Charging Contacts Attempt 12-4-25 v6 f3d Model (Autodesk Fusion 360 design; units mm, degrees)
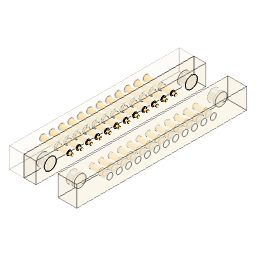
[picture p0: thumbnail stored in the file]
derived_base_feature "Derived Base Feature1" bodies "Male Pin 1"
copy_paste_bodies "CopyPasteBodies2"
move "Move2"
copy_paste_bodies "CopyPasteBodies4"
move "Move3"
copy_paste_bodies "CopyPasteBodies5"
move "Move4"
copy_paste_bodies "CopyPasteBodies6"
move "Move5"
derived_base_feature "Derived Base Feature2" bodies "Magnet (1)", "Magnet 1"
move "Move6"
move "Move7"
move "Move8"
move "Move9"
move "Move10"
move "Move11"
move "Move12"
copy_paste_bodies "CopyPasteBodies7"
move "Move13"
move "Move14"
move "Move15"
move "Move16"
align "Align1"
move "Move17"
align "Align2"
move "Move18"
remove_body "RemoveBody1"
copy_paste_bodies "CopyPasteBodies8"
move "Move19"
move "Move20"
sketch "Sketch4" plane through (0, 0, 0) normal (1, 0, 0) x axis (0, 1, 0)
  line L1 (45.2245, 5) -> (-45.0911, 5)
  line L2 (45.2245, -6) -> (45.2245, 5)
  line L3 (-45.0911, -6) -> (45.2245, -6)
  line L4 (-45.0911, 5) -> (-45.0911, -6)
  horizontal L1
  vertical L2
  horizontal L3
  vertical L4
extrude "Extrude1" new body sketch "Sketch4" along normal blind 7.849 bodies "Charger with Extrusion Female Facing"
extrude "Extrude2" cut of existing geometry blind -1.524
copy_paste_bodies "CopyPasteBodies9"
move "Move21"
copy_paste_bodies "CopyPasteBodies10"
move "Move22"
combine "Combine1"
derived_base_feature "Derived Base Feature3" bodies "0436-0-15-15-03-27-10-0", "Female Pin 1"
move "Move23"
component_from_bodies "Body->Comp"
move "Move1"
extrude "Extrude3" new body of existing geometry blind 7.874 bodies "Charger with Extrusion Wire Side"
combine "Combine2"
align "Align1"
move "Move2"
copy_paste_bodies "CopyPasteBodies1"
move "Move3"
copy_paste_bodies "CopyPasteBodies2"
move "Move4"
copy_paste_bodies "CopyPasteBodies3"
move "Move5"
copy_paste_bodies "CopyPasteBodies4"
copy_paste_bodies "CopyPasteBodies5"
move "Move6"
copy_paste_bodies "CopyPasteBodies6"
move "Move7"
sketch "Sketch1" plane through (0, 0, 0) normal (1, 0, 0) x axis (0, 1, 0)
  line L1 (45, 5) -> (-45, 5)
  line L2 (45, -6) -> (45, 5)
  line L3 (-45, -6) -> (45, -6)
  line L4 (-45, 5) -> (-45, -6)
  horizontal L1
  vertical L2
  horizontal L3
  vertical L4
sketch "Sketch2" plane through (0, 0, 0) normal (1, 0, 0) x axis (0, 1, 0)
extrude "Extrude1" new body sketch "Sketch4" along normal blind 10 bodies "Female Charger"
move "Move8"
copy_paste_bodies "CopyPasteBodies7"
move "Move9"
copy_paste_bodies "CopyPasteBodies8"
move "Move10"
move "Move11"
copy_paste_bodies "CopyPasteBodies9"
extrude "Extrude2" new body of existing geometry blind 8
copy_paste_bodies "CopyPasteBodies10"
move "Move12"
copy_paste_bodies "CopyPasteBodies11"
move "Move13"
copy_paste_bodies "CopyPasteBodies12"
move "Move14"
copy_paste_bodies "CopyPasteBodies13"
copy_paste_bodies "CopyPasteBodies14"
move "Move15"
combine "Combine1" bodies "Female Charger (1)", "Female Charger (2)", "Female Charger", "Female Charger (4)", "Female Charger (5)", "Female Charger (6)", "Female Charger (7)", "Female Charger (8)"
move "Move16"
move "Move17"
remove_body "RemoveBody1"
remove_body "RemoveBody2"
remove_body "RemoveBody3"
remove_body "RemoveBody4"
remove_body "RemoveBody5"
remove_body "RemoveBody6"
remove_body "RemoveBody7"
remove_body "RemoveBody8"
remove_body "RemoveBody9"
remove_body "RemoveBody10"
remove_body "RemoveBody11"
remove_body "RemoveBody12"
remove_body "RemoveBody13"
remove_body "RemoveBody14"
remove_body "RemoveBody15"
remove_body "RemoveBody16"
remove_body "RemoveBody17"
remove_body "RemoveBody18"
remove_body "RemoveBody19"
remove_body "RemoveBody20"
remove_body "RemoveBody21"
remove_body "RemoveBody22"
remove_body "RemoveBody23"
remove_body "RemoveBody24"
remove_body "RemoveBody25"
remove_body "RemoveBody26"
remove_body "RemoveBody27"
remove_body "RemoveBody28"
remove_body "RemoveBody29"
remove_body "RemoveBody30"
remove_body "RemoveBody31"
remove_body "RemoveBody32"
remove_body "RemoveBody33"
remove_body "RemoveBody34"
remove_body "RemoveBody35"
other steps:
base_feature "Base Feature1" bodies "Female Pin 1"
base_feature "Base Feature2" bodies "Male Pin 1", "Male Pin 2"
base_feature "Base Feature4" bodies "Male Pin 2", "Male Pin 1 (1)", "Male Pin 4", "Male Pin 3"
base_feature "Base Feature5" bodies "Male Pin 1 (2)", "Male Pin 2 (1)", "Male Pin 5", "Male Pin 6"
base_feature "Base Feature6" bodies "Male Pin 1 (3)", "Male Pin 2 (2)", "Male Pin 5", "Male Pin 6", "Male Pin 4", "Male Pin 3", "Male Pin 7", "Male Pin 8"
base_feature "Base Feature2" bodies "Female Pin 1 (1)", "Female Pin 2"
base_feature "Base Feature3" bodies "Female Pin 2", "Female Pin 3"
base_feature "Base Feature4" bodies "Female Pin 3", "Female Pin 2 (1)", "Female Pin 1 (2)", "Female Pin 6", "Female Pin 5", "Female Pin 4"
base_feature "Base Feature5" bodies "Female Magnet 1"
base_feature "Base Feature6" bodies "Female Pin 1 (3)", "Female Pin 2 (2)", "Female Pin 3 (1)", "Female Pin 4", "Female Pin 5", "Female Pin 6", "Female Pin 7", "Female Pin 8"
base_feature "Base Feature7" bodies "Female Magnet 1 (1)", "Female Magnet 2"
base_feature "Base Feature7" bodies "Magnet 1", "Magnet 2"
base_feature "Base Feature8" bodies "Magnet 1 (1)", "Magnet 1"
base_feature "Base Feature8" bodies "Female Magnet 1 (2)", "Female Magnet 1 Spacer"
base_feature "Base Feature9" bodies "Female Magnet 2", "Female Magnet 2 Spacer"
base_feature "Base Feature10" bodies "Female Pin 1 (4)", "Female Pin Extender"
base_feature "Base Feature11"
base_feature "Base Feature12"
base_feature "Base Feature13"
base_feature "Base Feature14"
base_feature "Base Feature15"
base_feature "Base Feature9" bodies "Magnet 2", "Magnet 2 Spacer"
base_feature "Base Feature10" bodies "Magnet 1 (2)", "Magnet 1 Spacer"
create_component "CreateComponent1"
reparent_decal "ReparentDecal1"
remove_body "RemoveBody2"
named bodies: "Male Pin 1", "Male Pin 2", "Male Pin 1 (1)", "Male Pin 4", "Male Pin 3", "Male Pin 1 (2)", "Male Pin 2 (1)", "Male Pin 5", "Male Pin 6", "Male Pin 1 (3)", "Male Pin 2 (2)", "Male Pin 7", "Male Pin 8", "Male Pin 11", "Male Pin 12", "Male Pin 10", "Male Pin 9", "Magnet (1)", "Magnet 1", "Magnet 2", "Magnet 1 (1)", "Charger with Extrusion Female Facing", "Magnet 2 Spacer", "Magnet 1 (2)", "Magnet 1 Spacer", "0436-0-15-15-03-27-10-0", "Female Pin 1", "Charger with Extrusion Wire Side", "Female Pin 1 (1)", "Female Pin 2", "Female Pin 3", "Female Pin 2 (1)", "Female Pin 1 (2)", "Female Pin 6", "Female Pin 5", "Female Pin 4", "Female Magnet 1", "Female Pin 1 (3)", "Female Pin 2 (2)", "Female Pin 3 (1)", "Female Pin 7", "Female Pin 8", "Female Pin 9", "Female Pin 10", "Female Pin 11", "Female Pin 12", "Female Magnet 1 (1)", "Female Magnet 2", "Female Charger", "Female Magnet 1 (2)", "Female Magnet 1 Spacer", "Female Magnet 2 Spacer", "Female Pin 1 (4)", "Female Pin Extender", "Female Charger (1)", "Female Charger (2)", "Female Charger (4)", "Female Charger (5)", "Female Charger (6)", "Female Charger (7)"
